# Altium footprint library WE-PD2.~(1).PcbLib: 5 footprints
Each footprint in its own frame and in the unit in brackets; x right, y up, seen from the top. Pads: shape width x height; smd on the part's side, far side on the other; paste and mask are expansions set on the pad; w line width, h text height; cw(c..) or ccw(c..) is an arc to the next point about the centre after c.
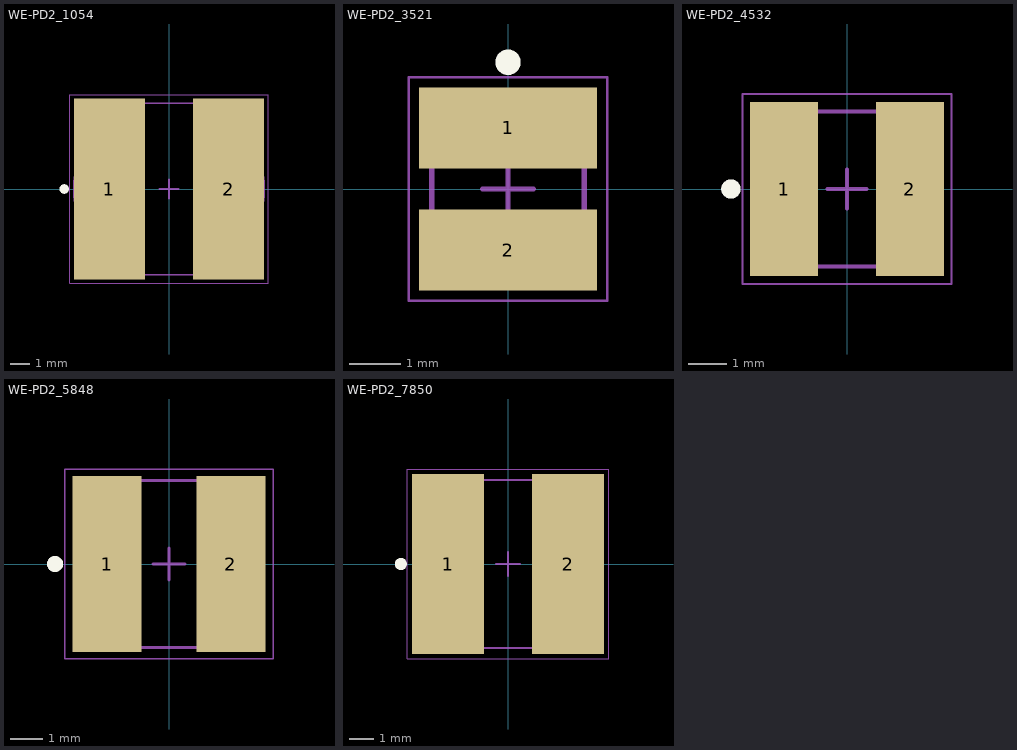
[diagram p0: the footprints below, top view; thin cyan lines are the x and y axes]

## WE-PD2_1054 [mm] "SMD Power Inductor, 2-Leads, body 10x9mm"
height 5.4
pads (2):
  rect 3.75x9.5 smd: 1(-3.125,0) 2(3.125,0)
Top Overlay:
  circle w0.25: c-5.5,0 r0.125
Top Assembly:
  circle w0.1: c-3.8,0 r0.5
  lines w0.1: -1.75,-4.5 cw(c-0.26,0) -1.75,4.5 1.75,4.5 cw(c0.26,0) 1.75,-4.5 -1.75,-4.5
Top Designator:
  text ".Designator" at -3.647,-0.357 h1
Top 3D Body:
  circle w0.1: c-3.8,0 r0.5
  lines w0.1: -1.75,-4.5 cw(c-0.26,0) -1.75,4.5 1.75,4.5 cw(c0.26,0) 1.75,-4.5 -1.75,-4.5
Top Courtyard:
  lines w0.05: -5.2,-4.95 -5.2,4.95 5.2,4.95 5.2,-4.95 -5.2,-4.95
Top Component Center:
  lines w0.1: -0.5,0 0.5,0 ; 0,-0.5 0,0.5
3D body "744776xx.stp": height 5.43, standoff 0.03, extent -5.045,-4.5 5.044,4.5

## WE-PD2_3521 [mm] "SMD Power Inductor, 2-Leads, body 3x3.5mm"
height 2.4
pads (2):
  rect 3.5x1.6 smd: 1(0,1.2) 2(0,-1.2)
Top Overlay:
  circle w0.25: c0,2.493 r0.125
Top Assembly:
  circle w0.1: c0,1.15 r0.2
  lines w0.1: -1.5,-0.8 ccw(c0,-0.091) 1.5,-0.8 1.5,0.8 ccw(c0,0.091) -1.5,0.8 -1.5,-0.8
Top Designator:
  text ".Designator" at -3.647,-0.357 h1
Top 3D Body:
  circle w0.1: c0,1.15 r0.2
  lines w0.1: -1.5,-0.8 ccw(c0,-0.091) 1.5,-0.8 1.5,0.8 ccw(c0,0.091) -1.5,0.8 -1.5,-0.8
Top Courtyard:
  lines w0.05: -1.95,-2.2 -1.95,2.2 1.95,2.2 1.95,-2.2 -1.95,-2.2
Top Component Center:
  lines w0.1: -0.5,0 0.5,0 ; 0,-0.5 0,0.5
3D body "744773xxx.stp": height 2.12, standoff 0.03, extent -1.5,-1.675 1.5,1.675

## WE-PD2_4532 [mm] "SMD Power Inductor, 2-Leads, body 4.5x4mm"
height 3.5
pads (2):
  rect 1.75x4.5 smd: 1(-1.625,0) 2(1.625,0)
Top Overlay:
  circle w0.25: c-3,0 r0.125
Top Assembly:
  circle w0.1: c-1.7,0 r0.25
  lines w0.1: -1,-2 cw(c-0.025,0) -1,2 1,2 cw(c0.025,0) 1,-2 -1,-2
Top Designator:
  text ".Designator" at -3.647,-0.357 h1
Top 3D Body:
  circle w0.1: c-1.7,0 r0.25
  lines w0.1: -1,-2 cw(c-0.025,0) -1,2 1,2 cw(c0.025,0) 1,-2 -1,-2
Top Courtyard:
  lines w0.05: -2.7,-2.45 -2.7,2.45 2.7,2.45 2.7,-2.45 -2.7,-2.45
Top Component Center:
  lines w0.1: -0.5,0 0.5,0 ; 0,-0.5 0,0.5
3D body "744773xxx.stp": height 3.22, standoff 0.02, extent -2.25,-2 2.25,2

## WE-PD2_5848 [mm] "SMD Power Inductor, 2-Leads, body 5.8x5.2mm"
height 4.85
pads (2):
  rect 2.15x5.5 smd: 1(-1.925,0) 2(1.925,0)
Top Overlay:
  circle w0.25: c-3.55,0 r0.125
Top Assembly:
  circle w0.1: c-2.3,0 r0.25
  lines w0.1: -1.5,-2.6 cw(c0.214,0) -1.5,2.6 1.5,2.6 cw(c-0.214,0) 1.5,-2.6 -1.5,-2.6
Top Designator:
  text ".Designator" at -3.647,-0.357 h1
Top 3D Body:
  circle w0.1: c-2.3,0 r0.25
  lines w0.1: -1.5,-2.6 cw(c0.214,0) -1.5,2.6 1.5,2.6 cw(c-0.214,0) 1.5,-2.6 -1.5,-2.6
Top Courtyard:
  lines w0.05: -3.25,-2.95 -3.25,2.95 3.25,2.95 3.25,-2.95 -3.25,-2.95
Top Component Center:
  lines w0.1: -0.5,0 0.5,0 ; 0,-0.5 0,0.5
3D body "744774xx.stp": height 4.48, standoff -0.02, extent -2.898,-2.6 2.889,2.6

## WE-PD2_7850 [mm] "SMD Power Inductor, 2-Leads, body 7.8x7mm"
height 5.45
pads (2):
  rect 3x7.5 smd: 1(-2.5,0) 2(2.5,0)
Top Overlay:
  circle w0.25: c-4.467,0 r0.125
Top Assembly:
  circle w0.1: c-3.3,0 r0.25
  lines w0.1: -1.7,-3.5 cw(c-0.016,0) -1.7,3.5 1.7,3.5 cw(c0.016,0) 1.7,-3.5 -1.7,-3.5
Top Designator:
  text ".Designator" at -3.647,-0.357 h1
Top 3D Body:
  circle w0.1: c-3.3,0 r0.25
  lines w0.1: -1.7,-3.5 cw(c-0.016,0) -1.7,3.5 1.7,3.5 cw(c0.016,0) 1.7,-3.5 -1.7,-3.5
Top Courtyard:
  lines w0.05: -4.2,-3.95 4.2,-3.95 4.2,3.95 -4.2,3.95 -4.2,-3.95
Top Component Center:
  lines w0.1: -0.5,0 0.5,0 ; 0,-0.5 0,0.5
3D body "744775xx.stp": height 4.95, standoff 0, extent -3.813,-3.5 3.813,3.5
